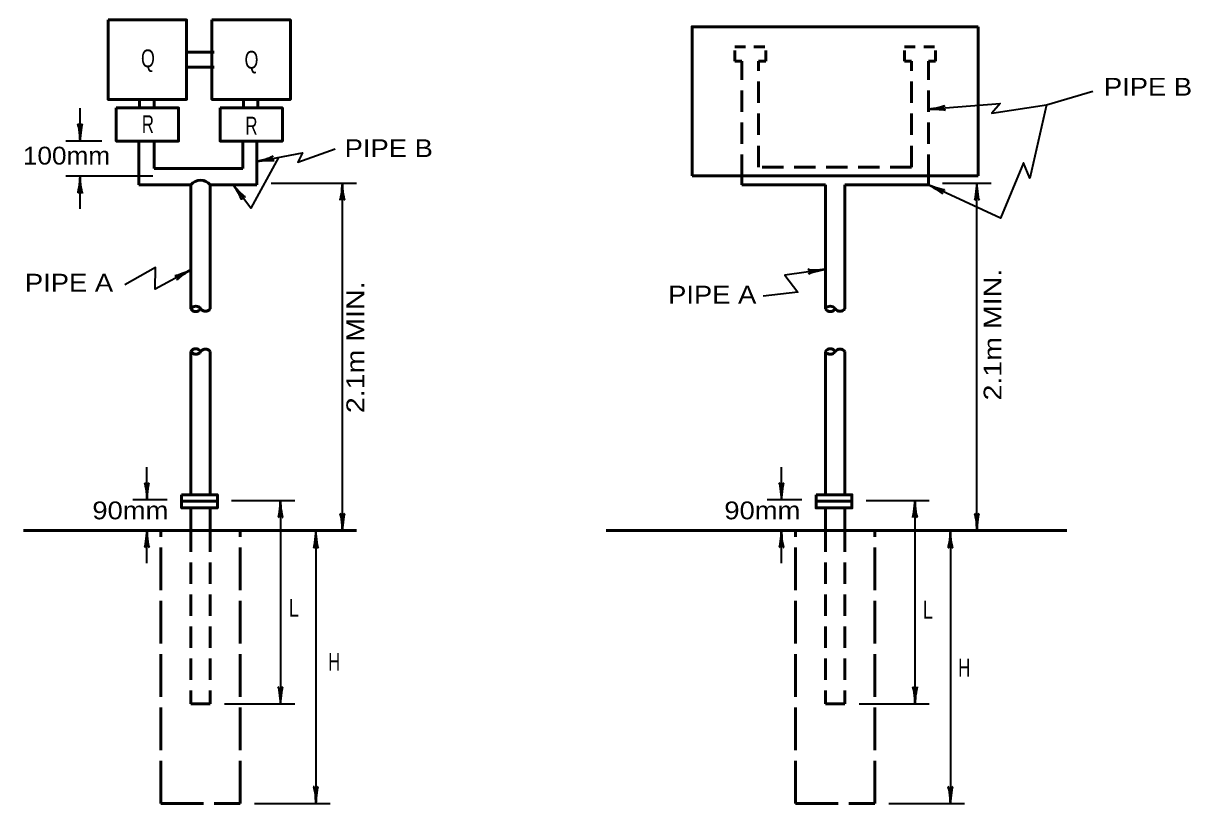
# Model space of a CAD drawing. Extents: x 11 to 867, y -284 to 260.
# Drawn here: x 431.9 to 628.7, y -13.7 to 117.8 of the extents above; entities that cross this region are included whole.
import ezdxf
from ezdxf.enums import TextEntityAlignment as Align

# ---------------------------------------------------------------- set-up
doc = ezdxf.new("R2010")
doc.units = 0
doc.header["$LTSCALE"] = 1.2
for name, pattern in [('LONG_DASHED', [7.5, 6, -1.5]), ('MEDIUM_DASHED', [4.5, 3, -1.5]), ('SHORT_DASHED', [2.7, 1.5, -1.2])]:
    doc.linetypes.add(name, pattern=pattern)
doc.layers.add('1', color=7, linetype='Continuous', lineweight=53)

msp = doc.modelspace()

# ---------------------------------------------------------------- linework, layer by layer
at = {"layer": '1'}
for p, q in [((592.901, 117.243), (592.901, 92.105)), ((464.085, 112.956), (459.473, 112.956)), ((464.085, 110.448), (459.473, 110.448)), ((451.529, 105.005), (451.529, 103.567)), ((453.973, 105.005), (453.973, 103.567)), ((469.031, 105.005), (469.031, 103.567)), ((471.475, 105.005), (471.475, 103.567)), ((451.391, 90.611), (451.391, 97.967)), ((453.995, 93.355), (453.995, 97.967)), ((468.965, 93.355), (468.965, 97.967)), ((471.327, 90.611), (471.327, 97.967)), ((453.995, 93.355), (468.965, 93.355)), ((451.391, 90.611), (460.189, 90.611)), ((460.189, 69.707), (460.189, 90.611)), ((463.463, 69.707), (463.463, 90.611)), ((463.463, 90.611), (471.301, 90.611)), ((584.501, 92.105), (544.671, 92.105)), ((553.071, 90.611), (553.071, 92.105)), ((567.149, 90.611), (553.071, 90.611)), ((567.149, 69.707), (567.149, 90.611)), ((570.423, 69.707), (570.423, 90.611)), ((584.501, 90.611), (570.423, 90.611)), ((592.901, 92.105), (584.501, 92.105)), ((584.501, 90.611), (584.501, 92.105)), ((460.191, 62.471), (460.191, 38.358)), ((463.463, 62.471), (463.463, 38.358)), ((567.151, 62.471), (567.151, 38.358)), ((570.423, 62.471), (570.423, 38.358)), ((458.605, 37.241), (464.659, 37.241)), ((460.191, 36.12), (460.191, 32.333)), ((463.463, 36.12), (463.463, 32.333)), ((565.565, 37.241), (571.619, 37.241)), ((567.151, 36.12), (567.151, 32.333)), ((570.423, 36.12), (570.423, 32.333)), ((431.945, 32.333), (488.125, 32.333)), ((530.199, 32.333), (607.851, 32.333))]:
    msp.add_line(p, q, dxfattribs=at)
at = {"layer": '1', "linetype": 'SHORT_DASHED'}
for p, q in [((551.871, 111.463), (551.871, 113.863)), ((551.871, 113.863), (557.095, 113.863)), ((557.095, 111.463), (557.095, 113.863)), ((580.477, 111.463), (580.477, 113.863)), ((580.477, 113.863), (585.701, 113.863)), ((585.701, 111.463), (585.701, 113.863)), ((553.071, 111.463), (551.871, 111.463)), ((557.095, 111.463), (555.895, 111.463)), ((581.677, 111.463), (580.477, 111.463)), ((585.701, 111.463), (584.501, 111.463))]:
    msp.add_line(p, q, dxfattribs=at)
at = {"layer": '1', "linetype": 'MEDIUM_DASHED'}
for p, q in [((553.071, 92.105), (553.071, 111.463)), ((581.677, 93.597), (581.677, 111.463)), ((584.501, 92.105), (584.501, 111.463)), ((460.191, 32.333), (460.191, 3.099)), ((463.463, 32.333), (463.463, 3.099)), ((567.151, 32.333), (567.151, 3.099)), ((570.423, 32.333), (570.423, 3.099)), ((460.191, 3.099), (463.463, 3.099)), ((567.151, 3.099), (570.423, 3.099))]:
    msp.add_line(p, q, dxfattribs=at)
at = {"layer": '1', "lineweight": 35}
for p, q in [((604.435, 104.065), (612.247, 106.385)), ((441.505, 97.999), (441.505, 103.499)), ((445.195, 97.967), (439.105, 97.967)), ((453.791, 92.038), (439.105, 92.038)), ((441.505, 86.538), (441.505, 92.038)), ((473.727, 90.861), (488.125, 90.861)), ((485.725, 32.333), (485.725, 90.861)), ((586.901, 90.861), (595.085, 90.861)), ((592.685, 32.333), (592.685, 90.861)), ((452.777, 37.489), (452.777, 43.001)), ((559.737, 37.489), (559.737, 43.001)), ((456.205, 37.489), (450.377, 37.489)), ((563.165, 37.489), (557.337, 37.489)), ((467.059, 37.381), (477.689, 37.381)), ((475.289, 37.381), (475.289, 3.099)), ((574.019, 37.381), (584.649, 37.381)), ((582.249, 37.381), (582.249, 3.099)), ((452.777, 26.821), (452.777, 32.333)), ((481.257, 32.206), (481.257, -13.726)), ((559.737, 26.821), (559.737, 32.333)), ((588.217, 32.206), (588.217, -13.726)), ((465.863, 3.099), (477.689, 3.099)), ((572.823, 3.099), (584.649, 3.099)), ((470.893, -13.726), (483.657, -13.726)), ((577.853, -13.726), (590.617, -13.726))]:
    msp.add_line(p, q, dxfattribs=at)
at = {"layer": '1', "linetype": 'LONG_DASHED'}
for p, q in [((455.129, -13.726), (455.129, 32.333)), ((562.089, -13.726), (562.089, 32.333))]:
    msp.add_line(p, q, dxfattribs=at)
at = {"layer": '1'}
for points in [[(446.235, 118.399), (459.473, 118.399), (459.473, 105.005), (446.235, 105.005)], [(463.737, 118.399), (476.975, 118.399), (476.975, 105.005), (463.737, 105.005)], [(447.595, 103.567), (458.111, 103.567), (458.111, 97.967), (447.595, 97.967)], [(465.097, 103.567), (475.613, 103.567), (475.613, 97.967), (465.097, 97.967)], [(458.605, 38.358), (464.659, 38.358), (464.659, 36.12), (458.605, 36.12)], [(565.565, 38.358), (571.619, 38.358), (571.619, 36.12), (565.565, 36.12)]]:
    msp.add_lwpolyline(points, close=True, dxfattribs=at)
msp.add_lwpolyline([(592.901, 117.243), (544.671, 117.243), (544.671, 92.105)], dxfattribs=at)
at = {"layer": '1', "linetype": 'MEDIUM_DASHED'}
msp.add_lwpolyline([(581.677, 93.597), (555.895, 93.597), (555.895, 111.463)], dxfattribs=at)
at = {"layer": '1', "lineweight": 35}
for points in [[(584.469, 103.337), (596.593, 104.306), (595.219, 102.689), (604.435, 104.065), (601.605, 91.695), (600.555, 94.281), (596.675, 84.983), (584.501, 90.611)], [(471.327, 94.532), (479.023, 95.969), (478.237, 94.397), (484.523, 96.689)], [(474.947, 95.209), (470.315, 86.669), (467.309, 90.611)], [(460.189, 76.264), (454.159, 73.031), (454.229, 76.654), (449.073, 73.727)], [(567.107, 76.339), (560.331, 75.389), (562.527, 72.505), (556.637, 71.823)]]:
    msp.add_lwpolyline(points, dxfattribs=at)
at = {"layer": '1', "linetype": 'LONG_DASHED'}
for points in [[(455.129, -13.726), (468.493, -13.726), (468.493, 32.333)], [(562.089, -13.726), (575.453, -13.726), (575.453, 32.333)]]:
    msp.add_lwpolyline(points, dxfattribs=at)
at = {"layer": '1'}
for centre, radius, start, end in [((461.826, 89.228), 2.143, 40.17606, 139.82394), ((461.009, 69.15), 0.989, 34.21419, 145.78581), ((461.009, 70.145), 0.928, 208.21086, 331.78914), ((462.645, 70.286), 1.003, 215.33373, 324.66627), ((567.969, 69.15), 0.989, 34.21419, 145.78581), ((567.969, 70.145), 0.928, 208.21086, 331.78914), ((569.605, 70.286), 1.003, 215.33373, 324.66627), ((461.009, 62.032), 0.928, 28.21086, 151.78914), ((461.009, 63.027), 0.989, 214.21419, 325.78581), ((462.645, 61.891), 1.003, 35.33373, 144.66627), ((567.969, 62.032), 0.928, 28.21086, 151.78914), ((567.969, 63.027), 0.989, 214.21419, 325.78581), ((569.605, 61.891), 1.003, 35.33373, 144.66627)]:
    msp.add_arc(centre, radius, start, end, dxfattribs=at)
at = {"layer": '1', "lineweight": 40}
for centre, major_axis, ratio, start_param, end_param in [((585.534, 103.699), (-1.768, -0.298), 0.122415, 0.8963533, 3.1415927), ((585.534, 103.699), (-1.768, -0.298), 0.122415, 0.8963533, 3.1415927), ((585.603, 103.215), (-1.765, 0.035), 0.07063, 3.1407148, 5.41811), ((585.603, 103.215), (-1.765, 0.035), 0.07063, 3.1407148, 5.41811), ((441.229, 99.09), (0.156, -1.786), 0.122415, 0.8963533, 3.1415927), ((441.229, 99.09), (0.156, -1.786), 0.122415, 0.8963533, 3.1415927), ((441.716, 99.119), (-0.176, -1.756), 0.07063, 3.1407148, 5.41811), ((441.716, 99.119), (-0.176, -1.756), 0.07063, 3.1407148, 5.41811), ((472.349, 95.004), (-1.727, -0.481), 0.122415, 0.8963533, 3.1415927), ((472.349, 95.004), (-1.727, -0.481), 0.122415, 0.8963533, 3.1415927), ((472.467, 94.53), (-1.759, -0.15), 0.07063, 3.1407148, 5.41811), ((472.467, 94.53), (-1.759, -0.15), 0.07063, 3.1407148, 5.41811), ((441.293, 90.918), (0.176, 1.756), 0.07063, 3.1407148, 5.41811), ((441.781, 90.947), (-0.156, 1.786), 0.122415, 0.8963533, 3.1415927), ((467.82, 89.591), (-0.925, 1.503), 0.07063, 3.1407148, 5.41811), ((468.19, 89.91), (-1.207, 1.325), 0.122415, 0.8963533, 3.1415927), ((485.513, 89.74), (0.176, 1.756), 0.07063, 3.1407148, 5.41811), ((486.001, 89.769), (-0.156, 1.786), 0.122415, 0.8963533, 3.1415927), ((585.429, 89.948), (-1.521, 0.896), 0.07063, 3.1407148, 5.41811), ((585.607, 90.403), (-1.686, 0.608), 0.122415, 0.8963533, 3.1415927), ((592.473, 89.74), (0.176, 1.756), 0.07063, 3.1407148, 5.41811), ((592.961, 89.769), (-0.156, 1.786), 0.122415, 0.8963533, 3.1415927), ((459.101, 75.921), (1.631, 0.675), 0.07063, 3.1407148, 5.41811), ((459.358, 75.505), (1.5, 0.982), 0.122415, 0.8963533, 3.1415927), ((565.989, 76.46), (1.79, 0.093), 0.122415, 3.1415927, 5.386832), ((566.027, 75.973), (1.715, 0.418), 0.07063, 0.8650754, 3.1424706), ((452.501, 38.58), (0.156, -1.786), 0.122415, 0.8963533, 3.1415927), ((452.501, 38.58), (0.156, -1.786), 0.122415, 0.8963533, 3.1415927), ((452.988, 38.609), (-0.176, -1.756), 0.07063, 3.1407148, 5.41811), ((452.988, 38.609), (-0.176, -1.756), 0.07063, 3.1407148, 5.41811), ((559.461, 38.58), (0.156, -1.786), 0.122415, 0.8963533, 3.1415927), ((559.461, 38.58), (0.156, -1.786), 0.122415, 0.8963533, 3.1415927), ((559.948, 38.609), (-0.176, -1.756), 0.07063, 3.1407148, 5.41811), ((559.948, 38.609), (-0.176, -1.756), 0.07063, 3.1407148, 5.41811), ((475.077, 36.26), (0.176, 1.756), 0.07063, 3.1407148, 5.41811), ((475.565, 36.289), (-0.156, 1.786), 0.122415, 0.8963533, 3.1415927), ((582.037, 36.26), (0.176, 1.756), 0.07063, 3.1407148, 5.41811), ((582.525, 36.289), (-0.156, 1.786), 0.122415, 0.8963533, 3.1415927), ((485.449, 33.424), (0.156, -1.786), 0.122415, 0.8963533, 3.1415927), ((485.936, 33.453), (-0.176, -1.756), 0.07063, 3.1407148, 5.41811), ((592.409, 33.424), (0.156, -1.786), 0.122415, 0.8963533, 3.1415927), ((592.896, 33.453), (-0.176, -1.756), 0.07063, 3.1407148, 5.41811), ((452.565, 31.212), (0.176, 1.756), 0.07063, 3.1407148, 5.41811), ((453.053, 31.241), (-0.156, 1.786), 0.122415, 0.8963533, 3.1415927), ((481.045, 31.086), (0.176, 1.756), 0.07063, 3.1407148, 5.41811), ((481.533, 31.115), (-0.156, 1.786), 0.122415, 0.8963533, 3.1415927), ((559.525, 31.212), (0.176, 1.756), 0.07063, 3.1407148, 5.41811), ((560.013, 31.241), (-0.156, 1.786), 0.122415, 0.8963533, 3.1415927), ((588.005, 31.086), (0.176, 1.756), 0.07063, 3.1407148, 5.41811), ((588.493, 31.115), (-0.156, 1.786), 0.122415, 0.8963533, 3.1415927), ((475.013, 4.19), (0.156, -1.786), 0.122415, 0.8963533, 3.1415927), ((475.5, 4.219), (-0.176, -1.756), 0.07063, 3.1407148, 5.41811), ((581.973, 4.19), (0.156, -1.786), 0.122415, 0.8963533, 3.1415927), ((582.46, 4.219), (-0.176, -1.756), 0.07063, 3.1407148, 5.41811), ((480.981, -12.634), (0.156, -1.786), 0.122415, 0.8963533, 3.1415927), ((481.468, -12.605), (-0.176, -1.756), 0.07063, 3.1407148, 5.41811), ((587.941, -12.634), (0.156, -1.786), 0.122415, 0.8963533, 3.1415927), ((588.428, -12.605), (-0.176, -1.756), 0.07063, 3.1407148, 5.41811)]:
    msp.add_ellipse(centre, major_axis=major_axis, ratio=ratio, start_param=start_param, end_param=end_param, dxfattribs=at)

# ---------------------------------------------------------------- texts
at = {"layer": '1'}
for s, width, p in [('Q', 0.75, (452.944, 110.421)), ('Q', 0.75, (470.4, 110.183)), ('PIPE B', 1.15, (621.525, 105.631)), ('R', 0.7, (452.944, 99.312)), ('R', 0.7, (470.4, 99.074)), ('100mm', 1.1, (439.222, 94.018)), ('PIPE B', 1.15, (493.541, 95.273)), ('PIPE A', 1.15, (439.641, 72.597)), ('PIPE A', 1.15, (548.067, 70.584)), ('90mm', 1.15, (449.984, 34.205)), ('90mm', 1.15, (556.518, 34.205)), ('L', 0.75, (477.548, 17.79)), ('L', 0.75, (584.418, 17.461)), ('H', 0.7, (484.34, 8.689)), ('H', 0.7, (590.553, 7.702))]:
    msp.add_text(s, height=3, dxfattribs=dict(at, width=width)).set_placement(p, align=Align.CENTER)
at = {"layer": '1', "width": 1.2}
for p in [(596.825, 65.336), (489.403, 63.204)]:
    msp.add_text('2.1m MIN.', height=3, rotation=90, dxfattribs=at).set_placement(p, align=Align.CENTER)

doc.saveas('drawing.dxf')
